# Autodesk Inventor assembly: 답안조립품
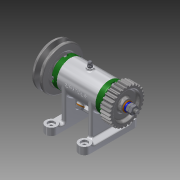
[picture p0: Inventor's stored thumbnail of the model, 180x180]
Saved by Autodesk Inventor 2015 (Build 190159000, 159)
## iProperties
Created: 2015-11
Part Number: 답안조립품
Document SubType Name: Assembly
Designer: Administrator
Author: Administrator
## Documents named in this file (16)
- C:\Users\Administrator\Desktop\451109V1037\답안조립품.iam
- C:\Users\Administrator\Desktop\451109V1037\1.본체.ipt
- C:\Users\Administrator\Desktop\451109V1037\와셔 6x11.5.ipt
- C:\Users\Administrator\Desktop\451109V1037\볼트 M 6 x 8.ipt
- C:\Users\Administrator\Desktop\451109V1037\니플 M 6 x 0.75.ipt
- C:\Users\Administrator\Desktop\451109V1037\베어링 15 x 32 x 9.ipt
- C:\Users\Administrator\Desktop\451109V1037\커버.ipt
- C:\Users\Administrator\Desktop\451109V1037\오일 실 15 25 7.ipt
- C:\Users\Administrator\Desktop\451109V1037\축.ipt
- C:\Users\Administrator\Desktop\451109V1037\스퍼기어.ipt
- C:\Users\Administrator\Desktop\451109V1037\키 3 x 3 x 12.ipt
- C:\Users\Administrator\Desktop\451109V1037\와셔 8x17.ipt
- C:\Users\Administrator\Desktop\451109V1037\스프링와셔 8.ipt
- C:\Users\Administrator\Desktop\451109V1037\너트 M 8.ipt
- C:\Users\Administrator\Desktop\451109V1037\V벨트풀리.ipt
- C:\Users\Administrator\Desktop\451109V1037\볼트 M4 x 12.ipt
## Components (12 placed, 4 different names)
1. 1.본체:1 — 각도:1, 각도:2, 각도:5, 각도:6, 각도:9, 각도:10, 각도:11, 각도:12
2. KS B 2023 6002 - 15 x 32 x 9:1
3. KS B 2023 6002 - 15 x 32 x 9:2
4. V벨트풀리:1 — 각도:8
5. ISO 4762 M4 x 12:1 — 각도:11
6. ISO 4762 M4 x 12:2
7. ISO 4762 M4 x 12:3
8. ISO 4762 M4 x 12:4
9. ISO 4762 M4 x 12:5 — 각도:12
10. ISO 4762 M4 x 12:6
11. ISO 4762 M4 x 12:7
12. ISO 4762 M4 x 12:8
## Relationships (9: Angle 9)
- 각도:1 [Angle]: 1.본체:1
- 각도:2 [Angle]: 1.본체:1
- 각도:5 [Angle]: 1.본체:1
- 각도:6 [Angle]: 1.본체:1
- 각도:8 [Angle]: V벨트풀리:1
- 각도:9 [Angle]: 1.본체:1
- 각도:10 [Angle]: 1.본체:1
- 각도:11 [Angle]: 1.본체:1 ↔ ISO 4762 M4 x 12:1
- 각도:12 [Angle]: 1.본체:1 ↔ ISO 4762 M4 x 12:5
